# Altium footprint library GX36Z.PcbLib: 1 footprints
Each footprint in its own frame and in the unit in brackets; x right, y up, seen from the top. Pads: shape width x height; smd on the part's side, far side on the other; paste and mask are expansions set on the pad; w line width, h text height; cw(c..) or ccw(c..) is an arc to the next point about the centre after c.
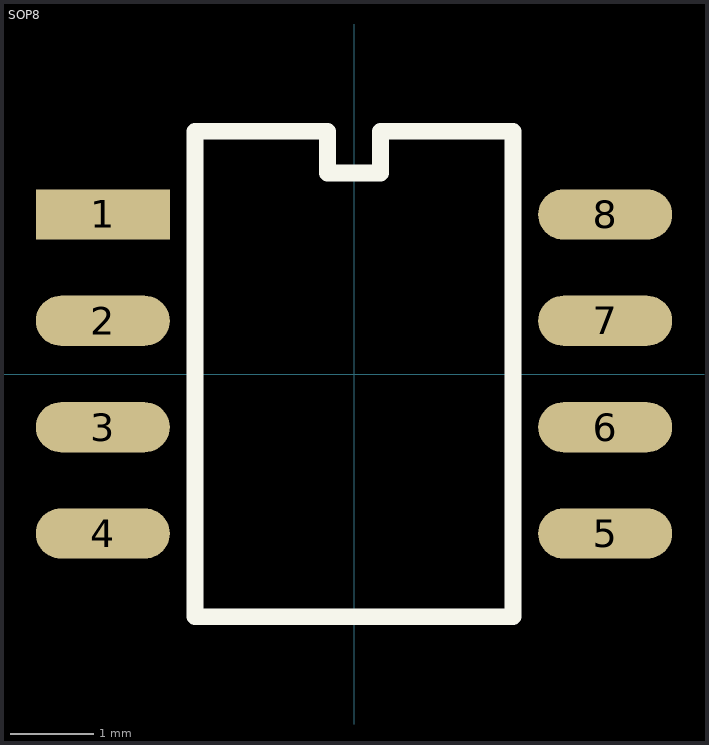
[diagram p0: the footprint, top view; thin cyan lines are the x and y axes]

## SOP8 [mm]
pads (8):
  rect 1.6x0.6 smd mask+0.025: 1(-3,1.905)
  oval 1.6x0.6 smd mask+0.025: 2(-3,0.635) 3(-3,-0.635) 4(-3,-1.905) 5(3,-1.905) 6(3,-0.635) 7(3,0.635) 8(3,1.905)
Top Overlay:
  lines w0.2: -1.9,-2.9 -1.9,2.9 -0.315,2.9 -0.315,2.4 0.315,2.4 0.315,2.9 1.9,2.9 1.9,-2.9 -1.9,-2.9
3D body "SOP8.STEP": height 1.72, standoff 0, extent -3.003,-2.427 2.997,2.388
